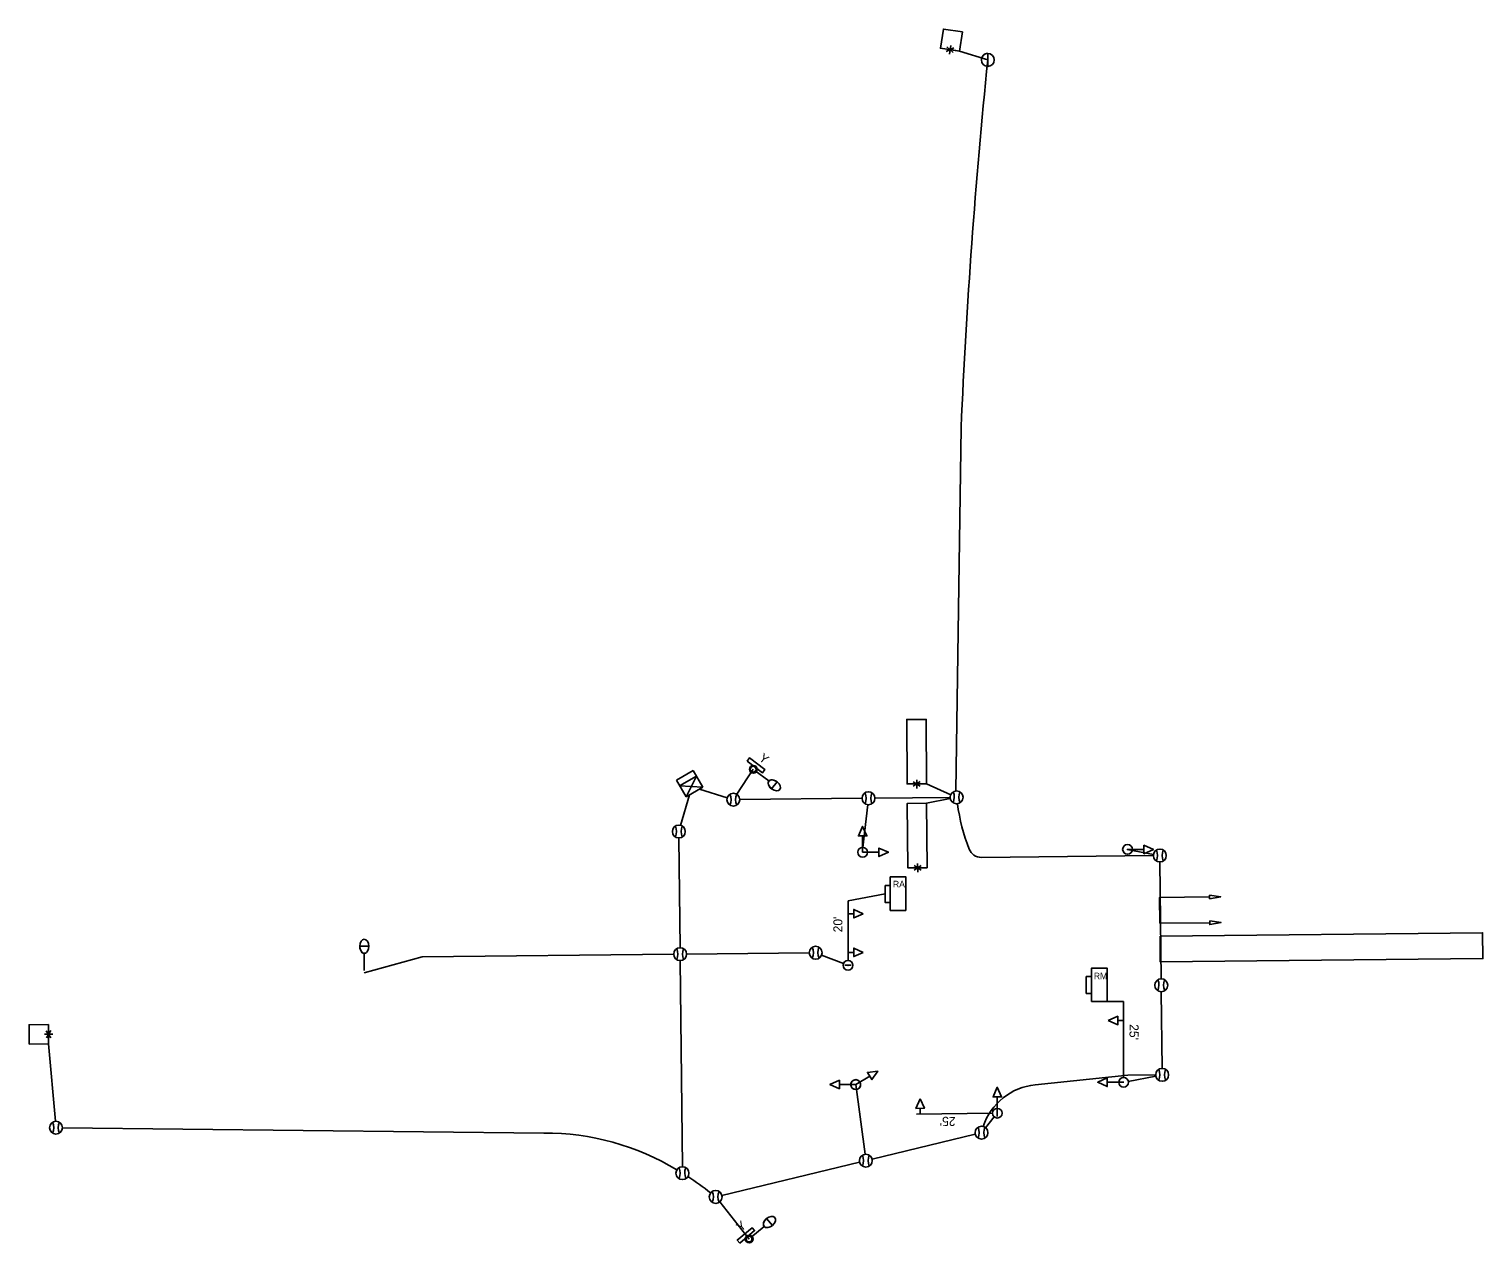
# Model space of a CAD drawing. Extents: x 596176 to 605330, y 332416 to 402398.
# Drawn here: x 602359.2 to 602809.7, y 387543.7 to 387920.7 of the extents above; entities that cross this region are included whole.
import ezdxf

# ---------------------------------------------------------------- set-up
doc = ezdxf.new("R2010")
doc.units = 0
for name, color, linetype in [('P_LTG', 7, 'Continuous'), ('P_SIG', 7, 'Continuous'), ('P_SIG_Bold', 7, 'Continuous'), ('P_SIG_Conduit', 7, 'Continuous'), ('P_SIG_Loops', 7, 'Continuous')]:
    doc.layers.add(name, color=color, linetype=linetype)

# ---------------------------------------------------------------- blocks, each defined once
blk = doc.blocks.new('_U309')
at = {"layer": 'P_SIG_Bold'}
for p, q in [((-3, 0), (-0.1, 0)), ((-0.1, 0.1), (0.1, -0.1)), ((0.1, 0.1), (-0.1, -0.1))]:
    blk.add_line(p, q, dxfattribs=at)
blk.add_circle((0, 0), 0.114, dxfattribs=at)
blk.add_text("40'", height=0.213, dxfattribs=at).set_placement((-1.9, 0.1))
blk = doc.blocks.new('_U321')
at = {"layer": 'P_LTG'}
for p, q in [((4.3, 25.1), (-4.1, 25.1)), ((0, 2.3), (0, 18.4))]:
    blk.add_line(p, q, dxfattribs=at)
blk.add_circle((0, 0.1), 3.68, dxfattribs=at)
blk.add_ellipse((0.1, 25.1), major_axis=(0, 6.65), ratio=0.636439, dxfattribs=at)
blk.add_ellipse((0.1, 25.1), major_axis=(0, 6.65), ratio=0.636439, start_param=1.570796, end_param=4.712389, dxfattribs=at)
blk = doc.blocks.new('_U322')
at = {"layer": 'P_LTG'}
for p, q in [((4.3, 25.1), (-4.1, 25.1)), ((0, 2.3), (0, 18.4))]:
    blk.add_line(p, q, dxfattribs=at)
blk.add_ellipse((0.1, 25.1), major_axis=(0, 6.65), ratio=0.636439, dxfattribs=at)
blk.add_ellipse((0.1, 25.1), major_axis=(0, 6.65), ratio=0.636439, start_param=1.570796, end_param=4.712389, dxfattribs=at)

msp = doc.modelspace()

# ---------------------------------------------------------------- linework, layer by layer
at = {"layer": 'P_SIG'}
for p, q in [((602656.31, 387913.11), (602656.29, 387909.11)), ((602581.71, 387693.74), (602582.44, 387694.7)), ((602586.49, 387690.11), (602581.71, 387693.74)), ((602582.44, 387694.7), (602587.22, 387691.06)), ((602559.78, 387687.78), (602564.96, 387690.8)), ((602562.8, 387682.59), (602559.78, 387687.78)), ((602560.79, 387686.05), (602565.97, 387689.07)), ((602562.8, 387682.59), (602565.97, 387689.07)), ((602564.96, 387690.8), (602567.99, 387685.62)), ((602587.22, 387691.06), (602586.49, 387690.11)), ((602567.99, 387685.62), (602560.79, 387686.05)), ((602567.99, 387685.62), (602562.8, 387682.59)), ((602617.5, 387670.51), (602617.49, 387665.46)), ((602622.55, 387665.44), (602617.49, 387665.46)), ((602704.66, 387666.31), (602699.6, 387666.33)), ((602624.45, 387652.53), (602612.98, 387650.41)), ((602614.75, 387646.41), (602612.98, 387646.41)), ((602614.77, 387634.41), (602612.99, 387634.41)), ((602693.26, 387619.22), (602698.37, 387619.13)), ((602696.6, 387613.29), (602698.37, 387613.31)), ((602610.31, 387593.44), (602615.37, 387593.43)), ((602619.69, 387596.07), (602615.37, 387593.43)), ((602693.31, 387594.14), (602698.37, 387594.13)), ((602659.25, 387589.61), (602659.24, 387584.55)), ((602635.33, 387586.07), (602635.35, 387584.3)), ((602578.65, 387545.19), (602583.24, 387549.05)), ((602584.01, 387548.13), (602579.42, 387544.27)), ((602583.24, 387549.05), (602584.01, 387548.13)), ((602579.42, 387544.27), (602578.65, 387545.19))]:
    msp.add_line(p, q, dxfattribs=at)
for points in [[(602656.29, 387909.11), (602656.31, 387913.11)], [(602617.5, 387673.47), (602618.82, 387670.51), (602616.18, 387670.51), (602617.5, 387673.47)], [(602618.82, 387670.51), (602617.5, 387673.47), (602616.18, 387670.51), (602618.82, 387670.51)], [(602625.51, 387665.44), (602622.55, 387664.13), (602622.55, 387666.76), (602625.51, 387665.44)], [(602622.55, 387664.13), (602625.51, 387665.44), (602622.55, 387666.76), (602622.55, 387664.13)], [(602707.62, 387666.31), (602704.66, 387665), (602704.66, 387667.63), (602707.62, 387666.31)], [(602704.66, 387665), (602707.62, 387666.31), (602704.66, 387667.63), (602704.66, 387665)], [(602622.21, 387597.62), (602620.38, 387594.95), (602619, 387597.19), (602622.21, 387597.62)], [(602620.38, 387594.95), (602622.21, 387597.62), (602619, 387597.19), (602620.38, 387594.95)], [(602607.35, 387593.44), (602610.31, 387594.76), (602610.31, 387592.12), (602607.35, 387593.44)], [(602610.31, 387594.76), (602607.35, 387593.44), (602610.31, 387592.12), (602610.31, 387594.76)], [(602659.25, 387592.57), (602660.57, 387589.61), (602657.93, 387589.61), (602659.25, 387592.57)], [(602659.25, 387592.57), (602660.57, 387589.61), (602657.93, 387589.61), (602659.25, 387592.57)], [(602660.57, 387589.61), (602659.25, 387592.57), (602657.93, 387589.61), (602660.57, 387589.61)], [(602690.35, 387594.14), (602693.31, 387595.46), (602693.31, 387592.82), (602690.35, 387594.14)], [(602690.35, 387594.14), (602693.31, 387595.46), (602693.31, 387592.82), (602690.35, 387594.14)], [(602693.31, 387595.46), (602690.35, 387594.14), (602693.31, 387592.82), (602693.31, 387595.46)]]:
    msp.add_lwpolyline(points, dxfattribs=at)
for points in [[(602581.71, 387693.74), (602582.44, 387694.7), (602587.22, 387691.06), (602586.49, 387690.11)], [(602630.91, 387647.44), (602630.91, 387657.79), (602626.08, 387657.79), (602626.08, 387647.44)], [(602624.45, 387655.17), (602626.05, 387655.17), (602626.05, 387649.89), (602624.45, 387649.89)], [(602617.71, 387646.41), (602614.75, 387645.09), (602614.75, 387647.72)], [(602617.72, 387634.41), (602614.77, 387633.09), (602614.77, 387635.72)], [(602693.26, 387619.22), (602693.26, 387629.56), (602688.44, 387629.56), (602688.44, 387619.22)], [(602686.81, 387626.94), (602688.4, 387626.94), (602688.4, 387621.67), (602686.81, 387621.67)], [(602693.64, 387613.26), (602696.58, 387614.61), (602696.61, 387611.97)], [(602635.3, 387589.03), (602636.65, 387586.08), (602634.01, 387586.05)], [(602579.42, 387544.27), (602578.65, 387545.19), (602583.24, 387549.05), (602584.01, 387548.13)]]:
    msp.add_lwpolyline(points, close=True, dxfattribs=at)
for centre, radius in [((602656.3, 387911.11), 2), ((602583.57, 387691.2), 0.9), ((602577.43, 387681.75), 2), ((602619.31, 387682.19), 2), ((602646.62, 387682.48), 2), ((602560.54, 387671.88), 2), ((602617.49, 387665.46), 1.52), ((602617.49, 387665.46), 1.52), ((602617.49, 387665.46), 1.52), ((602617.49, 387665.46), 1.52), ((602617.49, 387665.46), 1.52), ((602617.49, 387665.46), 1.52), ((602699.6, 387666.33), 1.52), ((602699.6, 387666.33), 1.52), ((602699.6, 387666.33), 1.52), ((602709.62, 387664.44), 2), ((602560.94, 387633.86), 2), ((602602.94, 387634.3), 2), ((602710.05, 387624.22), 2), ((602710.34, 387596.44), 2), ((602615.37, 387593.43), 1.52), ((602615.37, 387593.43), 1.52), ((602615.37, 387593.43), 1.52), ((602615.37, 387593.43), 1.52), ((602615.37, 387593.43), 1.52), ((602615.37, 387593.43), 1.52), ((602367.5, 387580.05), 2), ((602654.35, 387578.5), 2), ((602618.5, 387569.84), 2), ((602561.66, 387565.95), 2), ((602571.96, 387558.6), 2), ((602582.3, 387545.52), 0.9)]:
    msp.add_circle(centre, radius, dxfattribs=at)
for centre, radius, start, end in [((602656.3, 387911.11), 2, 89.7008, 180), ((602656.3, 387911.11), 2, 180, 269.7008), ((602572.36, 387681.78), 4.36, 336.6741, 22.5272), ((602582.5, 387681.79), 4.36, 157.5751, 203.4282), ((602614.24, 387682.23), 4.36, 336.6741, 22.5272), ((602624.38, 387682.24), 4.36, 157.5751, 203.4282), ((602641.55, 387682.52), 4.36, 336.6741, 22.5272), ((602651.69, 387682.53), 4.36, 157.5751, 203.4282), ((602555.46, 387671.91), 4.36, 336.6741, 22.5272), ((602565.61, 387671.92), 4.36, 157.5751, 203.4282), ((602617.49, 387665.46), 1.52, 0, 180), ((602617.49, 387665.46), 1.52, 90, 270), ((602617.49, 387665.46), 1.52, 180, 0), ((602617.49, 387665.46), 1.52, 270, 90), ((602699.6, 387666.33), 1.52, 0, 180), ((602699.6, 387666.33), 1.52, 180, 0), ((602704.55, 387664.47), 4.36, 336.6741, 22.5272), ((602714.69, 387664.48), 4.36, 157.5751, 203.4282), ((602555.87, 387633.89), 4.36, 336.6741, 22.5272), ((602566.01, 387633.9), 4.36, 157.5751, 203.4282), ((602597.87, 387634.34), 4.36, 336.6741, 22.5272), ((602608.01, 387634.35), 4.36, 157.5751, 203.4282), ((602704.98, 387624.26), 4.36, 336.6741, 22.5272), ((602715.12, 387624.27), 4.36, 157.5751, 203.4282), ((602705.27, 387596.48), 4.36, 336.6741, 22.5272), ((602715.41, 387596.48), 4.36, 157.5751, 203.4282), ((602615.37, 387593.43), 1.52, 0, 180), ((602615.37, 387593.43), 1.52, 31.5799, 211.5799), ((602615.37, 387593.43), 1.52, 180, 0), ((602615.37, 387593.43), 1.52, 211.5799, 31.5799), ((602362.43, 387580.09), 4.36, 336.6741, 22.5272), ((602372.57, 387580.09), 4.36, 157.5751, 203.4282), ((602649.28, 387578.54), 4.36, 336.6741, 22.5272), ((602659.42, 387578.55), 4.36, 157.5751, 203.4282), ((602613.43, 387569.88), 4.36, 336.6741, 22.5272), ((602623.57, 387569.89), 4.36, 157.5751, 203.4282), ((602556.59, 387565.98), 4.36, 336.6741, 22.5272), ((602566.73, 387565.99), 4.36, 157.5751, 203.4282), ((602566.89, 387558.64), 4.36, 336.6741, 22.5272), ((602577.03, 387558.65), 4.36, 157.5751, 203.4282)]:
    msp.add_arc(centre, radius, start, end, dxfattribs=at)
at = {"layer": 'P_SIG_Bold'}
for p, q in [((602612.98, 387650.41), (602612.98, 387631.91)), ((602698.37, 387619.13), (602698.37, 387595.63)), ((602634.24, 387584.29), (602657.74, 387584.53))]:
    msp.add_line(p, q, dxfattribs=at)
for centre in [(602612.98, 387630.41), (602698.37, 387594.13), (602659.24, 387584.55)]:
    msp.add_circle(centre, 1.5, dxfattribs=at)
at = {"layer": 'P_SIG_Conduit'}
for p, q in [((602578.47, 387683.46), (602583.59, 387691.19)), ((602563.86, 387683.21), (602561.1, 387673.79)), ((602575.5, 387682.29), (602566.95, 387685.01)), ((602621.31, 387682.21), (602644.62, 387682.46)), ((602617.31, 387682.17), (602579.43, 387681.77)), ((602617.57, 387666.95), (602619.08, 387680.21)), ((602560.56, 387669.83), (602560.92, 387635.86)), ((602699.51, 387666.33), (602707.66, 387664.8)), ((602710.03, 387626.22), (602709.64, 387662.44)), ((602562.94, 387633.88), (602600.94, 387634.28)), ((602604.8, 387633.58), (602611.58, 387630.95)), ((602560.96, 387631.86), (602561.64, 387567.95)), ((602710.32, 387598.44), (602710.07, 387622.2)), ((602618.24, 387571.83), (602615.37, 387593.43)), ((602708.38, 387596.06), (602699.84, 387594.41)), ((602655.61, 387580.06), (602658.3, 387583.38)), ((602620.45, 387570.31), (602652.41, 387578.03)), ((602573.91, 387559.07), (602616.56, 387569.37)), ((602573.2, 387557.04), (602582.32, 387545.53))]:
    msp.add_line(p, q, dxfattribs=at)
for points in [[(602648.03, 387797.12), (602646.43, 387684.47)], [(602654.3, 387663.85), (602707.62, 387664.41)], [(602463, 387628.07), (602480.98, 387633.01), (602558.94, 387633.83)], [(602670.96, 387593.36), (602699.65, 387596.32), (602708.34, 387596.42)], [(602369.5, 387580.01), (602518.69, 387578.39)]]:
    msp.add_lwpolyline(points, dxfattribs=at)
for centre, radius, start, end in [((604620.68, 387711.25), 1974.52, 174.19067, 177.50763), ((602710.24, 387689.44), 64, 188.0312, 201.0949), ((602654.26, 387667.85), 4, 201.0949, 270.6076), ((602672.92, 387574.46), 19, 95.905, 161.6722), ((602519.02, 387499.36), 79.03, 58.8144, 90.2371), ((602514.12, 387488.35), 91, 51.794, 57.2486)]:
    msp.add_arc(centre, radius, start, end, dxfattribs=at)
at = {"layer": 'P_SIG_Loops'}
for p, q in [((602645.78, 387914.86), (602643.41, 387913.77)), ((602645.57, 387913.42), (602643.63, 387915.14)), ((602644.4, 387912.94), (602644.8, 387915.58)), ((602644.59, 387914.3), (602647.55, 387913.85)), ((602647.55, 387913.85), (602656.3, 387911.11)), ((602635.36, 387687.37), (602633.19, 387685.93)), ((602635.37, 387685.92), (602633.19, 387687.32)), ((602634.29, 387685.26), (602634.28, 387687.94)), ((602634.26, 387686.63), (602637.26, 387686.64)), ((602637.26, 387686.67), (602644.79, 387683.3)), ((602644.66, 387682.1), (602637.33, 387680.67)), ((602635.65, 387659.93), (602633.46, 387661.31)), ((602635.63, 387661.38), (602633.47, 387659.93)), ((602634.57, 387659.26), (602634.54, 387661.94)), ((602634.54, 387660.64), (602637.54, 387660.67)), ((602365.19, 387609.03), (602365.16, 387612.03)), ((602366.56, 387609.06), (602363.89, 387609.03)), ((602364.45, 387610.11), (602365.9, 387607.95)), ((602365.9, 387610.14), (602364.52, 387607.95)), ((602365.22, 387606.03), (602367.32, 387582.04))]:
    msp.add_line(p, q, dxfattribs=at)
for points in [[(602647.55, 387913.85), (602648.45, 387919.78), (602642.52, 387920.68), (602641.62, 387914.75)], [(602637.26, 387686.64), (602637.2, 387706.64), (602631.2, 387706.63), (602631.26, 387686.63)], [(602637.54, 387660.67), (602637.33, 387680.67), (602631.33, 387680.6), (602631.54, 387660.6)], [(602725, 387652.18), (602728.51, 387651.63), (602725.01, 387651.01)], [(602725.08, 387644.18), (602728.59, 387643.63), (602725.1, 387643.01)], [(602709.67, 387639.43), (602709.75, 387631.43), (602809.75, 387632.49), (602809.66, 387640.49)], [(602365.16, 387612.03), (602359.16, 387611.96), (602359.22, 387605.96), (602365.22, 387606.03)]]:
    msp.add_lwpolyline(points, close=True, dxfattribs=at)
for points in [[(602725.01, 387651.59), (602709.54, 387651.43)], [(602709.54, 387651.43), (602709.54, 387651.43), (602709.63, 387643.43), (602709.63, 387643.43)], [(602725.09, 387643.6), (602709.63, 387643.43)]]:
    msp.add_lwpolyline(points, dxfattribs=at)

# ---------------------------------------------------------------- block references
at = {"layer": 'P_LTG', "xscale": 0.32808333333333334}
for name, p, yscale, rotation in [('_U321', (602583.59, 387691.19), 0.3280833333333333, -127.08364887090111), ('_U309', (602699.6, 387666.31), 0.32808333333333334, 180), ('_U309', (602612.98, 387630.41), 0.32808333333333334, 180), ('_U309', (602659.24, 387584.55), 0.32808333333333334, 90), ('_U321', (602582.32, 387545.53), 0.3280833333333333, -49.87014046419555)]:
    msp.add_blockref(name, p, dxfattribs=dict(at, yscale=yscale, rotation=rotation))
at = {"layer": 'P_LTG', "xscale": 0.32808333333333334, "yscale": 0.32808333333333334}
for name, p in [('_U322', (602463, 387628.07)), ('_U309', (602612.98, 387630.41)), ('_U309', (602698.37, 387594.18))]:
    msp.add_blockref(name, p, dxfattribs=at)

# ---------------------------------------------------------------- texts
at = {"layer": 'P_SIG'}
for s, height, rotation, p in [('Y', 2.8, 322.7651, (602585.1, 387694.13)), ('RA', 2, 360, (602626.9, 387654.6)), ('RM', 2, 360, (602689.16, 387626.1)), ('Y', 2.8, 39.9787, (602579.79, 387547.66))]:
    msp.add_text(s, height=height, rotation=rotation, dxfattribs=at).set_placement(p)
at = {"layer": 'P_SIG_Bold'}
for s, rotation, p in [("20'", 90, (602611.23, 387640.62)), ("25'", 269.3924, (602700.25, 387612.16)), ("25'", 179.4938, (602646.31, 387583.4))]:
    msp.add_text(s, height=2.8, rotation=rotation, dxfattribs=at).set_placement(p)

doc.saveas('drawing.dxf')
